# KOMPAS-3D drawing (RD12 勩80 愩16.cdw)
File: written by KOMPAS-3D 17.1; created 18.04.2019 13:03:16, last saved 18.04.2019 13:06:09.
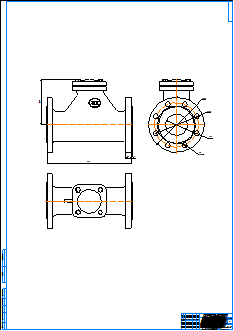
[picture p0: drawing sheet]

Sheet 1: A0, portrait

Title block, sheet 1: name: RD12 Ду80 Ру16; material: Внимание! Данный продукт является объектом авторского права ООО «Торговый Дом АДЛ». / Запрещается изменение, копирование, распространение / (в том числе путем копирования на другие сайты и ресурсы в Интернете) / или любое иное использование информации и объектов без предварительного / согласия правообладателя (ООО «Торговый Дом АДЛ»).; mass: 31,65; sheets: 1; organisation: ООО "Торговый дом АДЛ"; sheet format: A0

Views: Вид 1, Проекционный вид 2, Проекционный вид 3
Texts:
  user
Dimensions and other numbers on the sheet: 165; 21; 3; 304; 160; 200; 80; 18; 8 отв.; 1:1; 1; 31,65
